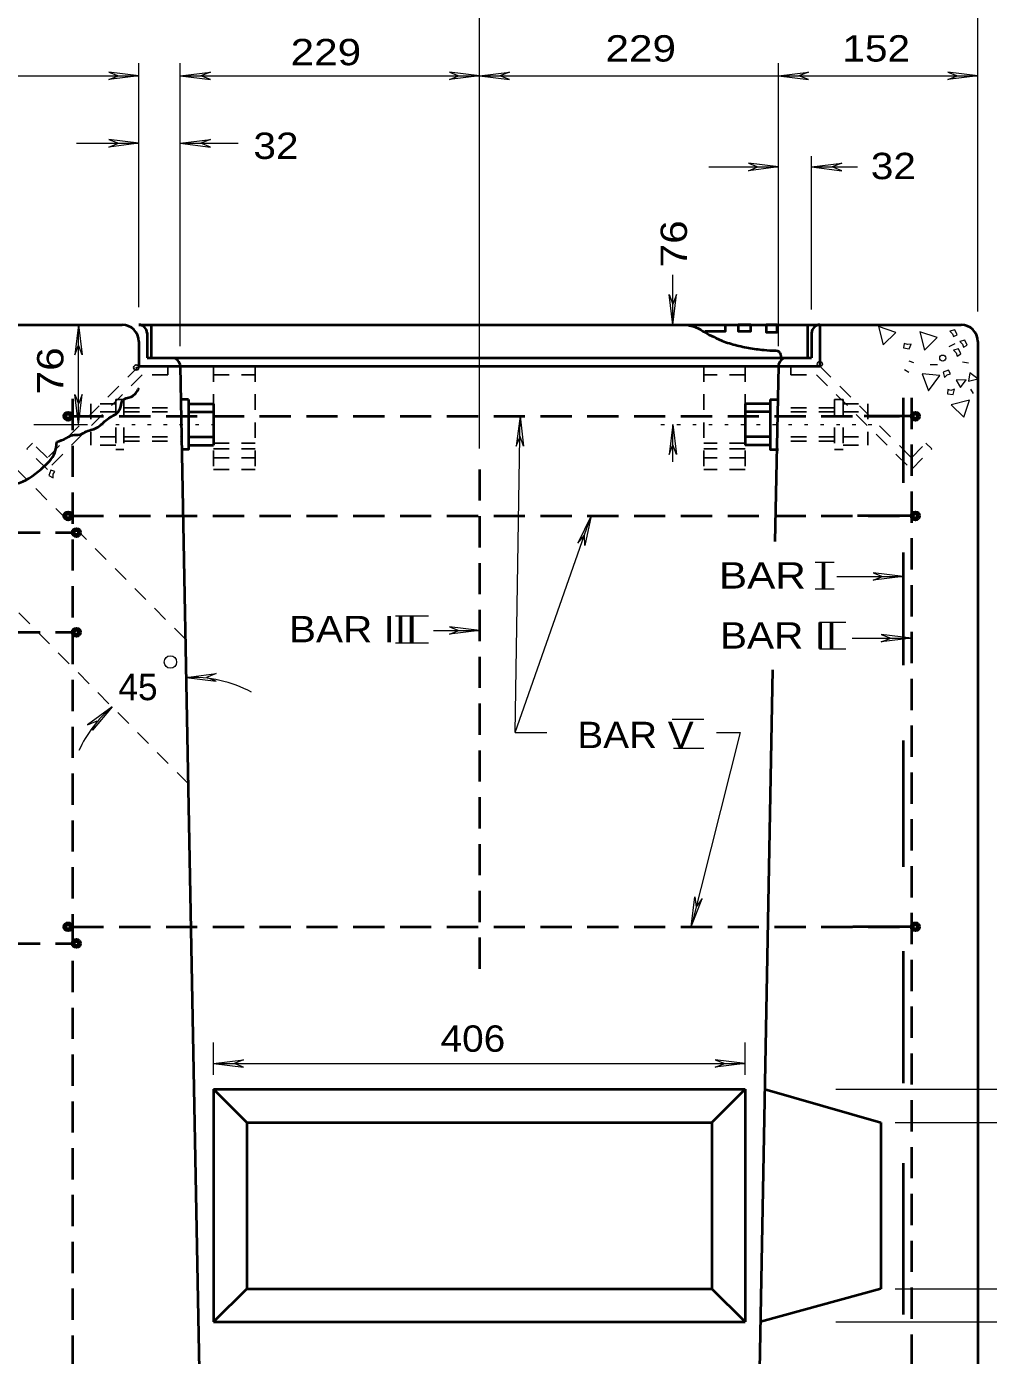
# Model space of a CAD drawing. Extents: x 312583 to 312854, y 144419 to 144597.
# Drawn here: x 312642.19 to 312669.93, y 144464.5 to 144502.81 of the extents above; entities that cross this region are included whole.
import ezdxf

# ---------------------------------------------------------------- set-up
doc = ezdxf.new("R2010")
doc.units = 0
doc.header["$LTSCALE"] = 0.3
doc.header["$PDMODE"] = 32
doc.header["$PDSIZE"] = 0.15
for name, pattern in [('DOTTED', [1.5, 0.3, -1.2]), ('MEDIUM_DASHED', [4.5, 3, -1.5]), ('SHORT_DASHED', [2.7, 1.5, -1.2])]:
    doc.linetypes.add(name, pattern=pattern)
doc.layers.add('1', color=7, linetype='Continuous', lineweight=25)
doc.layers.add('2', color=7, linetype='Continuous', lineweight=13)

msp = doc.modelspace()

# ---------------------------------------------------------------- linework, layer by layer
at = {"layer": '1', "lineweight": 40}
for p, q in [((312626.7325, 144494.2114), (312644.9408, 144494.2114)), ((312645.4238, 144494.2114), (312669.1368, 144494.2114)), ((312645.7765, 144494.2114), (312645.7765, 144493.2531)), ((312664.7055, 144494.2114), (312664.7055, 144493.2531)), ((312665.0658, 144494.2114), (312665.0658, 144493.0154)), ((312645.6615, 144493.9738), (312645.6615, 144493.2531)), ((312664.8281, 144493.9738), (312664.8281, 144493.2531)), ((312645.4238, 144493.7284), (312645.4238, 144493.0154)), ((312669.6198, 144493.7284), (312669.6198, 144451.0864)), ((312645.4238, 144493.0154), (312665.0658, 144493.0154)), ((312645.6615, 144493.2531), (312664.8281, 144493.2531)), ((312646.6198, 144493.0154), (312647.3405, 144454.9198)), ((312663.8698, 144493.0154), (312663.7701, 144487.9631)), ((312646.8575, 144492.0571), (312646.6198, 144492.0571)), ((312646.8575, 144491.9344), (312647.5781, 144491.9344)), ((312647.5781, 144491.9344), (312647.5781, 144490.7384)), ((312662.9115, 144491.9344), (312662.9115, 144490.7384)), ((312663.6321, 144491.9344), (312662.9115, 144491.9344)), ((312663.6321, 144492.0571), (312663.8698, 144492.0571)), ((312667.4655, 144492.1031), (312667.4655, 144489.6574)), ((312646.8575, 144491.6968), (312647.5781, 144491.6968)), ((312663.6321, 144491.6968), (312662.9115, 144491.6968)), ((312667.7031, 144491.5741), (312666.3461, 144491.5741)), ((312646.8575, 144490.9761), (312647.5781, 144490.9761)), ((312646.8575, 144490.7384), (312647.5781, 144490.7384)), ((312663.6321, 144490.9761), (312662.9115, 144490.9761)), ((312663.6321, 144490.7384), (312662.9115, 144490.7384)), ((312667.7031, 144488.6991), (312666.1545, 144488.6991)), ((312667.4655, 144487.6488), (312667.4655, 144484.3981)), ((312663.7011, 144484.2601), (312663.1491, 144454.9198)), ((312667.4655, 144482.2208), (312667.4655, 144478.5868)), ((312667.7031, 144476.8541), (312666.0165, 144476.8541)), ((312667.4655, 144476.1488), (312667.4655, 144472.3461)), ((312647.5781, 144472.1698), (312662.9115, 144472.1698)), ((312647.5781, 144472.1698), (312647.5781, 144465.4614)), ((312648.5365, 144471.2114), (312647.5781, 144472.1698)), ((312661.9531, 144471.2114), (312662.9115, 144472.1698)), ((312662.9115, 144472.1698), (312662.9115, 144465.4614)), ((312663.4788, 144472.1698), (312666.8215, 144471.2114)), ((312648.5365, 144471.2114), (312661.9531, 144471.2114)), ((312648.5365, 144471.2114), (312648.5365, 144466.4198)), ((312661.9531, 144471.2114), (312661.9531, 144466.4198)), ((312666.8215, 144471.2114), (312666.8215, 144466.4198)), ((312667.4655, 144470.0384), (312667.4655, 144465.6761)), ((312648.5365, 144466.4198), (312647.5781, 144465.4614)), ((312648.5365, 144466.4198), (312661.9531, 144466.4198)), ((312662.9115, 144465.4614), (312661.9531, 144466.4198)), ((312666.8215, 144466.4198), (312663.3485, 144465.4614)), ((312647.5781, 144465.4614), (312662.9115, 144465.4614))]:
    msp.add_line(p, q, dxfattribs=at)
at = {"layer": '1', "linetype": 'SHORT_DASHED'}
for p, q in [((312646.8421, 144480.9864), (312633.7168, 144494.2114)), ((312646.7655, 144485.1418), (312637.7648, 144494.2114)), ((312645.4238, 144493.0154), (312642.7865, 144490.3781)), ((312646.2595, 144493.0154), (312646.2595, 144492.7701)), ((312647.5781, 144493.0154), (312647.5781, 144490.0408)), ((312648.7741, 144493.0154), (312648.7741, 144490.0408)), ((312661.7155, 144493.0154), (312661.7155, 144490.0408)), ((312662.9115, 144493.0154), (312662.9115, 144490.0408)), ((312664.2301, 144493.0154), (312664.2301, 144492.7701)), ((312665.0658, 144493.0154), (312667.7031, 144490.3781)), ((312645.5235, 144492.7701), (312642.7865, 144490.0408)), ((312646.2595, 144492.7701), (312645.5235, 144492.7701)), ((312647.5781, 144492.7701), (312648.7741, 144492.7701)), ((312662.9115, 144492.7701), (312661.7155, 144492.7701)), ((312664.2301, 144492.7701), (312664.9661, 144492.7701)), ((312664.9661, 144492.7701), (312667.7031, 144490.0408)), ((312644.0361, 144491.9344), (312644.0361, 144490.7384)), ((312644.7568, 144491.9344), (312644.0361, 144491.9344)), ((312644.7568, 144492.0571), (312644.7568, 144490.6158)), ((312644.7568, 144492.0571), (312644.9945, 144492.0571)), ((312644.9945, 144492.0571), (312644.9945, 144490.6158)), ((312665.4875, 144492.0571), (312665.4875, 144490.6158)), ((312665.7328, 144492.0571), (312665.4875, 144492.0571)), ((312665.7328, 144492.0571), (312665.7328, 144490.6158)), ((312665.7328, 144491.9344), (312666.4458, 144491.9344)), ((312666.4458, 144491.9344), (312666.4458, 144490.7384)), ((312644.7568, 144491.6968), (312644.0361, 144491.6968)), ((312644.9945, 144491.8118), (312646.6198, 144491.8118)), ((312644.9945, 144491.6968), (312646.6198, 144491.6968)), ((312665.4875, 144491.8118), (312663.8698, 144491.8118)), ((312665.4875, 144491.6968), (312663.8698, 144491.6968)), ((312665.7328, 144491.6968), (312666.4458, 144491.6968)), ((312642.3571, 144490.7998), (312642.1885, 144490.6311)), ((312642.7865, 144490.3781), (312642.3571, 144490.7998)), ((312644.7568, 144490.9761), (312644.0361, 144490.9761)), ((312644.7568, 144490.7384), (312644.0361, 144490.7384)), ((312644.9945, 144490.9761), (312646.6198, 144490.9761)), ((312644.9945, 144490.8534), (312646.6198, 144490.8534)), ((312647.5781, 144490.7998), (312648.7741, 144490.7998)), ((312662.9115, 144490.7998), (312661.7155, 144490.7998)), ((312665.4875, 144490.9761), (312663.8698, 144490.9761)), ((312665.4875, 144490.8534), (312663.8698, 144490.8534)), ((312665.7328, 144490.9761), (312666.4458, 144490.9761)), ((312665.7328, 144490.7384), (312666.4458, 144490.7384)), ((312667.7031, 144490.3781), (312668.1248, 144490.7998)), ((312668.1248, 144490.7998), (312668.2935, 144490.6311)), ((312642.7865, 144490.0408), (312642.1885, 144490.6311)), ((312644.7568, 144490.6158), (312644.9945, 144490.6158)), ((312647.5781, 144490.6311), (312648.7741, 144490.6311)), ((312647.5781, 144490.3781), (312648.7741, 144490.3781)), ((312662.9115, 144490.6311), (312661.7155, 144490.6311)), ((312662.9115, 144490.3781), (312661.7155, 144490.3781)), ((312665.7328, 144490.6158), (312665.4875, 144490.6158)), ((312667.7031, 144490.0408), (312668.2935, 144490.6311)), ((312647.5781, 144490.0408), (312648.7741, 144490.0408)), ((312662.9115, 144490.0408), (312661.7155, 144490.0408))]:
    msp.add_line(p, q, dxfattribs=at)
at = {"layer": '1', "linetype": 'MEDIUM_DASHED', "lineweight": 40}
for p, q in [((312643.5071, 144492.0724), (312643.5071, 144452.3821)), ((312667.7031, 144492.1031), (312667.7031, 144452.3821)), ((312643.5071, 144491.5741), (312667.7031, 144491.5741)), ((312655.2448, 144490.0408), (312655.2448, 144475.3591)), ((312643.5071, 144488.6991), (312667.7031, 144488.6991)), ((312628.1738, 144488.2238), (312643.5071, 144488.2238)), ((312628.1738, 144485.3488), (312643.5071, 144485.3488)), ((312643.5071, 144476.8541), (312667.7031, 144476.8541)), ((312628.1738, 144476.3711), (312643.5071, 144476.3711))]:
    msp.add_line(p, q, dxfattribs=at)
at = {"layer": '1', "linetype": 'DOTTED', "lineweight": 13}
for p, q in [((312643.8368, 144491.3364), (312647.8695, 144491.3364)), ((312660.4811, 144491.3364), (312666.7755, 144491.3364))]:
    msp.add_line(p, q, dxfattribs=at)
at = {"layer": '1', "lineweight": 40}
for points in [[(312662.3365, 144494.2114), (312662.3365, 144494.0121), (312661.7615, 144494.0121)], [(312646.8575, 144492.0571), (312646.8575, 144490.6158), (312646.6658, 144490.6158)], [(312663.6321, 144492.0571), (312663.6321, 144490.6158), (312663.8698, 144490.6158)]]:
    msp.add_lwpolyline(points, dxfattribs=at)
for points in [[(312662.7121, 144494.2114), (312662.7121, 144494.0274), (312663.0725, 144494.0274), (312663.0725, 144494.2114)], [(312663.5171, 144494.2114), (312663.5171, 144493.9968), (312663.8315, 144493.9968), (312663.8315, 144494.2114)]]:
    msp.add_lwpolyline(points, close=True, dxfattribs=at)
at = {"layer": '1', "lineweight": 13}
msp.add_lwpolyline([(312642.9551, 144489.9028), (312643.0011, 144489.9794), (312642.8861, 144490.0178), (312642.8248, 144489.8644), (312642.9551, 144489.7954)], close=True, dxfattribs=at)
at = {"layer": '1', "lineweight": 40}
for centre, radius in [((312643.3835, 144491.5741), 0.1198), ((312643.3835, 144491.5741), 0.0838), ((312643.3835, 144491.5741), 0.0587), ((312667.821, 144491.5741), 0.1198), ((312667.821, 144491.5741), 0.0838), ((312667.821, 144491.5741), 0.0587), ((312643.3835, 144488.6991), 0.1198), ((312643.3835, 144488.6991), 0.0838), ((312667.821, 144488.6991), 0.1198), ((312667.821, 144488.6991), 0.0838), ((312643.3835, 144488.6991), 0.0587), ((312667.821, 144488.6991), 0.0587), ((312643.6231, 144488.2199), 0.1198), ((312643.6231, 144488.2199), 0.0838), ((312643.6231, 144488.2199), 0.0587), ((312643.6231, 144485.3449), 0.1198), ((312643.6231, 144485.3449), 0.0838), ((312643.6231, 144485.3449), 0.0587), ((312643.3835, 144476.8531), 0.1198), ((312643.3835, 144476.8531), 0.0838), ((312643.3835, 144476.8531), 0.0587), ((312667.821, 144476.8531), 0.1198), ((312667.821, 144476.8531), 0.0838), ((312667.821, 144476.8531), 0.0587), ((312643.6231, 144476.374), 0.1198), ((312643.6231, 144476.374), 0.0838), ((312643.6231, 144476.374), 0.0587)]:
    msp.add_circle(centre, radius, dxfattribs=at)
for centre, radius, start, end in [((312645.42, 144493.9699), 0.2396, 0, 90), ((312665.0658, 144493.9699), 0.2396, 90, 180), ((312669.1387, 144493.7303), 0.4792, 0, 90), ((312646.3783, 144493.0116), 0.2396, 0, 90), ((312664.1075, 144493.0116), 0.2396, 90, 180)]:
    msp.add_arc(centre, radius, start, end, dxfattribs=at)
for points in [[(312637.0135, 144494.2114), (312637.1898, 144493.4218), (312637.3431, 144493.2224), (312637.7111, 144492.8084), (312637.9948, 144492.3331), (312638.6695, 144491.3288), (312639.1678, 144490.5238), (312639.7581, 144490.2401), (312640.3638, 144489.8338), (312640.9771, 144489.7648), (312641.8895, 144489.6344), (312642.6025, 144490.0484), (312643.0011, 144490.5238), (312643.0625, 144490.8304)], [(312661.2478, 144494.2038), (312661.4548, 144494.1501), (312661.6311, 144494.0658), (312661.8765, 144493.9201), (312662.1371, 144493.7974), (312662.2905, 144493.7284), (312662.5128, 144493.6594), (312662.9498, 144493.5521), (312663.3868, 144493.4908), (312663.7011, 144493.4678), (312663.8775, 144493.4371), (312663.9465, 144493.2454)], [(312643.0625, 144490.8304), (312643.3231, 144490.9378), (312643.5148, 144491.0298), (312643.7295, 144491.0451), (312643.8675, 144491.1141), (312644.2048, 144491.2368), (312644.4808, 144491.4591), (312644.6495, 144491.5741), (312644.7875, 144491.6584), (312644.9025, 144491.8578), (312644.9485, 144492.0264), (312645.2015, 144492.1338), (312645.4315, 144492.3791)]]:
    msp.add_spline(points, degree=3, dxfattribs=at)
at = {"layer": '1'}
msp.add_point((312645.3471, 144492.9771), dxfattribs=at)
at = {"layer": '2'}
for p, q in [((312669.6198, 144494.5871), (312669.6198, 144505.4968)), ((312655.2448, 144490.6388), (312655.2448, 144503.5034)), ((312644.5575, 144501.4948), (312644.8335, 144501.3874)), ((312645.4238, 144501.3874), (312644.5575, 144501.4948)), ((312645.4238, 144494.7174), (312645.4238, 144501.7554)), ((312646.6198, 144493.5904), (312646.6198, 144501.7554)), ((312646.6198, 144501.3874), (312647.4861, 144501.4948)), ((312647.4861, 144501.4948), (312647.2101, 144501.3874)), ((312654.3785, 144501.4948), (312654.6545, 144501.3874)), ((312655.2448, 144501.3874), (312654.3785, 144501.4948)), ((312655.2448, 144501.3874), (312656.1111, 144501.4948)), ((312656.1111, 144501.4948), (312655.8351, 144501.3874)), ((312663.8698, 144493.5904), (312663.8698, 144501.7554)), ((312663.8698, 144501.3874), (312664.7361, 144501.4948)), ((312664.7361, 144501.4948), (312664.4601, 144501.3874)), ((312668.7535, 144501.4948), (312669.0295, 144501.3874)), ((312669.6198, 144501.3874), (312668.7535, 144501.4948)), ((312644.5575, 144501.2801), (312644.8335, 144501.3874)), ((312645.4238, 144501.3874), (312644.5575, 144501.2801)), ((312646.6198, 144501.3874), (312655.2448, 144501.3874)), ((312646.6198, 144501.3874), (312647.4861, 144501.2801)), ((312647.4861, 144501.2801), (312647.2101, 144501.3874)), ((312654.3785, 144501.2801), (312654.6545, 144501.3874)), ((312655.2448, 144501.3874), (312654.3785, 144501.2801)), ((312655.2448, 144501.3874), (312663.8698, 144501.3874)), ((312655.2448, 144501.3874), (312656.1111, 144501.2801)), ((312656.1111, 144501.2801), (312655.8351, 144501.3874)), ((312663.8698, 144501.3874), (312669.6198, 144501.3874)), ((312663.8698, 144501.3874), (312664.7361, 144501.2801)), ((312664.7361, 144501.2801), (312664.4601, 144501.3874)), ((312668.7535, 144501.2801), (312669.0295, 144501.3874)), ((312669.6198, 144501.3874), (312668.7535, 144501.2801)), ((312644.5575, 144499.5474), (312644.8335, 144499.4401)), ((312645.4238, 144499.4401), (312644.5575, 144499.5474)), ((312646.6198, 144499.4401), (312647.4861, 144499.5474)), ((312647.4861, 144499.5474), (312647.2101, 144499.4401)), ((312643.6221, 144499.4401), (312645.4238, 144499.4401)), ((312644.5575, 144499.3328), (312644.8335, 144499.4401)), ((312645.4238, 144499.4401), (312644.5575, 144499.3328)), ((312646.6198, 144499.4401), (312648.2911, 144499.4401)), ((312646.6198, 144499.4401), (312647.4861, 144499.3328)), ((312647.4861, 144499.3328), (312647.2101, 144499.4401)), ((312661.8611, 144498.7578), (312663.8698, 144498.7578)), ((312663.0035, 144498.8651), (312663.2795, 144498.7578)), ((312663.8698, 144498.7578), (312663.0035, 144498.8651)), ((312663.0035, 144498.6504), (312663.2795, 144498.7578)), ((312663.8698, 144498.7578), (312663.0035, 144498.6504)), ((312664.8281, 144494.6484), (312664.8281, 144499.0721)), ((312664.8281, 144498.7578), (312665.6945, 144498.8651)), ((312664.8281, 144498.7578), (312666.1545, 144498.7578)), ((312664.8281, 144498.7578), (312665.6945, 144498.6504)), ((312665.6945, 144498.8651), (312665.4185, 144498.7578)), ((312665.6945, 144498.6504), (312665.4185, 144498.7578)), ((312660.8261, 144494.2114), (312660.8261, 144495.6451)), ((312660.7188, 144495.0778), (312660.8261, 144494.8018)), ((312660.8261, 144494.2114), (312660.7188, 144495.0778)), ((312660.9335, 144495.0778), (312660.8261, 144494.8018)), ((312660.8261, 144494.2114), (312660.9335, 144495.0778)), ((312643.6835, 144494.2114), (312643.5761, 144493.3451)), ((312643.6835, 144491.3364), (312643.6835, 144494.2114)), ((312643.6835, 144494.2114), (312643.7908, 144493.3451)), ((312643.5761, 144493.3451), (312643.6835, 144493.6211)), ((312643.7908, 144493.3451), (312643.6835, 144493.6211)), ((312668.9528, 144493.6594), (312668.7841, 144493.5751)), ((312667.6265, 144493.1688), (312667.7645, 144493.1228)), ((312668.4545, 144493.0538), (312668.2475, 144493.0538)), ((312669.3515, 144493.0998), (312669.1751, 144493.1304)), ((312667.5038, 144492.9234), (312667.6341, 144492.8391)), ((312669.4971, 144492.2258), (312669.4205, 144492.3561)), ((312643.5761, 144492.2028), (312643.6835, 144491.9268)), ((312643.6835, 144491.3364), (312643.5761, 144492.2028)), ((312643.7908, 144492.2028), (312643.6835, 144491.9268)), ((312643.6835, 144491.3364), (312643.7908, 144492.2028)), ((312656.2798, 144482.4584), (312656.4255, 144491.5741)), ((312656.4255, 144491.5741), (312656.3028, 144490.7078)), ((312656.4255, 144491.5741), (312656.5175, 144490.7078)), ((312642.3955, 144491.3364), (312643.9441, 144491.3364)), ((312660.8261, 144491.3364), (312660.7188, 144490.4701)), ((312660.8261, 144491.3364), (312660.9335, 144490.4701)), ((312660.8261, 144490.2554), (312660.8261, 144491.3364)), ((312656.3028, 144490.7078), (312656.4178, 144490.9838)), ((312656.5175, 144490.7078), (312656.4178, 144490.9838)), ((312660.7188, 144490.4701), (312660.8261, 144490.7461)), ((312660.9335, 144490.4701), (312660.8261, 144490.7461)), ((312656.2798, 144482.4584), (312658.4725, 144488.6991)), ((312658.4725, 144488.6991), (312658.0815, 144487.9171)), ((312658.4725, 144488.6991), (312658.2885, 144487.8481)), ((312658.0815, 144487.9171), (312658.2731, 144488.1394)), ((312658.2885, 144487.8481), (312658.2731, 144488.1394)), ((312664.9278, 144487.3664), (312665.4798, 144487.3664)), ((312665.5565, 144486.9511), (312667.4655, 144486.9511)), ((312666.5991, 144487.0584), (312666.8751, 144486.9511)), ((312667.4655, 144486.9511), (312666.5991, 144487.0584)), ((312666.5991, 144486.8438), (312666.8751, 144486.9511)), ((312667.4655, 144486.9511), (312666.5991, 144486.8438)), ((312664.9278, 144486.5951), (312665.4798, 144486.5951)), ((312652.8298, 144485.8154), (312653.7805, 144485.8154)), ((312653.9261, 144485.3948), (312655.2448, 144485.3948)), ((312654.3785, 144485.5021), (312654.6545, 144485.3948)), ((312655.2448, 144485.3948), (312654.3785, 144485.5021)), ((312654.3785, 144485.2874), (312654.6545, 144485.3948)), ((312655.2448, 144485.3948), (312654.3785, 144485.2874)), ((312665.0581, 144485.6393), (312665.8171, 144485.6393)), ((312652.8298, 144485.0433), (312653.7805, 144485.0433)), ((312665.9935, 144485.1724), (312667.7031, 144485.1724)), ((312666.8368, 144485.2798), (312667.1128, 144485.1724)), ((312667.7031, 144485.1724), (312666.8368, 144485.2798)), ((312666.8368, 144485.0651), (312667.1128, 144485.1724)), ((312667.7031, 144485.1724), (312666.8368, 144485.0651)), ((312665.0581, 144484.868), (312665.8171, 144484.868)), ((312646.7885, 144484.0378), (312647.6548, 144484.1528)), ((312646.7885, 144484.0378), (312647.6548, 144483.9381)), ((312647.6548, 144484.1528), (312647.3788, 144484.0378)), ((312647.6548, 144483.9381), (312647.3788, 144484.0378)), ((312644.6495, 144483.1944), (312643.9441, 144482.6808)), ((312644.6495, 144483.1944), (312644.0898, 144482.5198)), ((312643.9441, 144482.6808), (312644.2201, 144482.7881)), ((312644.0898, 144482.5198), (312644.2201, 144482.7881)), ((312660.8029, 144482.8375), (312661.7155, 144482.8375)), ((312656.2798, 144482.4584), (312657.1921, 144482.4584)), ((312662.7658, 144482.4584), (312661.3551, 144476.8541)), ((312662.0835, 144482.4584), (312662.7658, 144482.4584)), ((312660.8415, 144482.0041), (312661.7155, 144482.0041)), ((312661.3551, 144476.8541), (312661.4625, 144477.7204)), ((312661.4625, 144477.7204), (312661.5008, 144477.4291)), ((312661.3551, 144476.8541), (312661.6695, 144477.6668)), ((312661.6695, 144477.6668), (312661.5008, 144477.4291)), ((312647.5781, 144472.5838), (312647.5781, 144473.5191)), ((312662.9115, 144472.5838), (312662.9115, 144473.5191)), ((312647.5781, 144472.9134), (312648.4445, 144473.0208)), ((312647.5781, 144472.9134), (312662.9115, 144472.9134)), ((312647.5781, 144472.9134), (312648.4445, 144472.8061)), ((312648.4445, 144473.0208), (312648.1685, 144472.9134)), ((312648.4445, 144472.8061), (312648.1685, 144472.9134)), ((312662.0451, 144473.0208), (312662.3211, 144472.9134)), ((312662.9115, 144472.9134), (312662.0451, 144473.0208)), ((312662.0451, 144472.8061), (312662.3211, 144472.9134)), ((312662.9115, 144472.9134), (312662.0451, 144472.8061)), ((312665.5258, 144472.1698), (312676.5581, 144472.1698)), ((312667.2355, 144471.2114), (312674.9328, 144471.2114)), ((312667.2355, 144466.4198), (312674.9328, 144466.4198)), ((312665.5258, 144465.4614), (312676.5581, 144465.4614))]:
    msp.add_line(p, q, dxfattribs=at)
msp.add_lwpolyline([(312626.2571, 144501.3874), (312635.8405, 144501.3874), (312645.4238, 144501.3874)], dxfattribs=at)
for points in [[(312666.8905, 144493.6288), (312667.2585, 144493.9891), (312666.7601, 144494.1578)], [(312668.0865, 144493.4754), (312668.4468, 144493.8434), (312667.9485, 144494.0044)], [(312668.8915, 144493.9508), (312668.9145, 144493.8664), (312669.0218, 144493.9201), (312668.9605, 144494.0658), (312668.8148, 144494.0274)], [(312669.1828, 144493.6518), (312669.2058, 144493.5674), (312669.3131, 144493.6211), (312669.2441, 144493.7668), (312669.1061, 144493.7284)], [(312667.5881, 144493.6364), (312667.4961, 144493.6671), (312667.4808, 144493.5444), (312667.6418, 144493.5138), (312667.6955, 144493.6518)], [(312668.9988, 144493.3988), (312669.0218, 144493.3068), (312669.1291, 144493.3681), (312669.0678, 144493.5138), (312668.9221, 144493.4754)], [(312668.5235, 144492.7471), (312668.0175, 144492.7931), (312668.2015, 144492.3024)], [(312668.7381, 144492.7701), (312668.8301, 144492.7931), (312668.7765, 144492.9004), (312668.6231, 144492.8391), (312668.6615, 144492.6934)], [(312668.9988, 144492.6091), (312669.1215, 144492.4021), (312669.2825, 144492.6244)], [(312669.3898, 144492.8238), (312669.3515, 144492.5861), (312669.6198, 144492.6474)], [(312668.8378, 144492.3178), (312668.7535, 144492.3408), (312668.7458, 144492.2181), (312668.9068, 144492.2028), (312668.9451, 144492.3484)], [(312668.8531, 144491.9038), (312669.2135, 144491.5434), (312669.3821, 144492.0341)]]:
    msp.add_lwpolyline(points, close=True, dxfattribs=at)
for centre, radius in [((312668.6071, 144493.2499), 0.0865), ((312646.334, 144484.4862), 0.1797)]:
    msp.add_circle(centre, radius, dxfattribs=at)
at = {"layer": '2', "lineweight": 40}
msp.add_arc((312644.9408, 144493.7303), 0.4792, 0, 90, dxfattribs=at)
at = {"layer": '2'}
for start, end in [(61.86121, 92.97681), (130.14212, 155.493)]:
    msp.add_arc((312646.9744, 144480.4383), 3.6044, start, end, dxfattribs=at)
msp.add_point((312665.0658, 144493.0768), dxfattribs=at)

# ---------------------------------------------------------------- texts
for s, width, p in [('229 ', 1.2, (312649.8005, 144501.6903)), ('229 ', 1.2, (312658.8814, 144501.7967)), ('152 ', 1.15, (312665.7147, 144501.7967)), ('32 ', 1.15, (312648.7281, 144498.9896)), ('32 ', 1.15, (312666.535, 144498.407)), ('BAR I', 1.2, (312662.1532, 144486.6042)), ('BAR III', 1.15, (312649.7529, 144485.0554)), ('BAR II', 1.15, (312662.1843, 144484.8739)), ('BAR V', 1.1, (312658.0705, 144482.0047)), ('406', 1.1, (312654.1261, 144473.2517))]:
    msp.add_text(s, height=0.76, dxfattribs=dict(at, width=width)).set_placement(p)
at = {"layer": '2', "width": 1.2}
for p in [(312661.2317, 144495.8646), (312643.2483, 144492.2027)]:
    msp.add_text('76 ', height=0.76, rotation=90, dxfattribs=at).set_placement(p)
at = {"layer": '2'}
msp.add_text('45', height=0.76, dxfattribs=at).set_placement((312644.8337, 144483.387))

doc.saveas('drawing.dxf')
